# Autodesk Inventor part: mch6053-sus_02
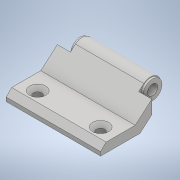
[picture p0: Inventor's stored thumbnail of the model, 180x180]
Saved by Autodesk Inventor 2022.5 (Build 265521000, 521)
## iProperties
Part Number: mch6053-sus_02
Material: 一般
Document SubType Name: Modeling
Designer: ImaoCorp
Density: 1 g/cm^3
Appearance: 既定
Author: ImaoCorp
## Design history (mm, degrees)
feature "mch6053-sus_02"
node "ソリッド1"
